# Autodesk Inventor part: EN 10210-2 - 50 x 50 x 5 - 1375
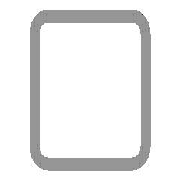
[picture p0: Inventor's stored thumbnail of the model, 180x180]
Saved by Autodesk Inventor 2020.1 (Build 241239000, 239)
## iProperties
IsCustomPart: 1
_CCFamilyMember: 16
_CCFamilyDisplayName: DIN EN 10210-2 (USAS B17.1 quadratisch) - Rohrleitung — In Klammern angegebene Größen wurden aufgehoben
_FrameMemberDoc: Frame Member File
_Version: 15.0.0
_GetPNFromCC: 1
Created: 2019-01
Part Number: EN 10210-2 - 50 x 50 x 5 - 1375
Material: Stahl, weich
Description: Rohrleitung
Document SubType Name: Modeling
Standard: DIN
Designer: lutzd
Standard Revision: 2006-07
Standards Organization: DIN
Language: de-DE
Size Designation: 50 x 50 x 5
Categories: <MemberInstance><Categories><Category DisplayName="Profile" InternalName="089c4875-fa83-4c05-b084-43b9cc11f5ed" Mnemonic="GRDR"><CategoryParameter DisplayName="
Stock Number: 50 x 50 x 5
Mass: 9422.11 g
Surface Area: 4673.09 cm^2
Volume: 1200.27 cm^3
Density: 7.85 g/cm^3
Appearance: Semi-Polished(8)
G_L: 1375,000 mm
G_W: 50,000 mm
G_H: 50,000 mm
DocNumber: ADSK-014303
Folder: .
Dimensions: 50x50x1375 mm
Mass: 9,422 kg
VLT_Material: Stahl, weich
Title: Profil-Bauteil
Author: lutzd
Revision Number: -
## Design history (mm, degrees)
node "Startebene"
node "Endebene"
sketch "Skizze"
  geometry: L1 (-25, -17.5)-(-25, 17.5); L2 (-17.5, 25)-(17.5, 25); L3 (25, 17.5)-(25, -17.5); L4 (17.5, -25)-(-17.5, -25); L5 (-15, 20)-(15, 20); L6 (20, 15)-(20, -15); L7 (15, -20)-(-15, -20); L8 (-20, -15)-(-20, 15); L9 (0, 37.175)-(0, -37.175) reference; L10 (-37.175, 0)-(37.175, 0) reference; A1 r 7.5 centre (-17.5, -17.5) between (-25, -17.5) and (-17.5, -25); A2 r 7.5 centre (-17.5, 17.5) between (-17.5, 25) and (-25, 17.5); A3 r 7.5 centre (17.5, 17.5) between (25, 17.5) and (17.5, 25); A4 r 7.5 centre (17.5, -17.5) between (17.5, -25) and (25, -17.5); A5 r 5 centre (-15, -15) between (-20, -15) and (-15, -20); A6 r 5 centre (-15, 15) between (-15, 20) and (-20, 15); A7 r 5 centre (15, 15) between (20, 15) and (15, 20); A8 r 5 centre (15, -15) between (15, -20) and (20, -15)
  constraints: 16 end point, 16 point on circle, 16 tangent, 8 centre point, 6 equal radius, 4 parallel, 2 perpendicular, 2 other
  dimensions: "d7" = 7.5 radius of A1 (= G_IR); "d10" = 50 distance between parallel lines of L2 L4 (= G_H); "d11" = 50 distance between parallel lines of L1 L3 (= G_W); "d12" = 5 distance between parallel lines of L3 L6 (= G_T); "d15" = 25 distance between parallel lines of L2 L10 (= 0.5 x d10); "d16" = 25 distance between parallel lines of L9 L3 (= 0.5 x d11); "d19" = 5 radius of A5 (= G_T); "d20" = 5 distance between parallel lines of L4 L7 (= G_T)
extrude "Körper" new body sketch "Skizze" stored distance "d3" = 1375 (= G_L); taper "d4" = 0 deg
node "Driven Length"
  sketch "Sketch3"
    geometry: L1 (0, 0)-(10, 0) reference
    constraints: 2 end point, 1 horizontal
  workplane "Work Plane3"
  sketch "Sketch4"
    geometry: L1 (-2, 0)-(12, 0) reference; L2 (-2, 1375)-(12, 1375) reference
    dimensions: "d18" = 1375 distance between parallel lines of L1 L2 (derived)
sketch "Skizze5"
  geometry: L1 (-29.5, 785)-(-5.5, 785); L2 (-35, 0)-(0, 0) reference; 5 further points
  constraints: 2 coincident, 2 end point, 2 midpoint, 1 horizontal, 1 vertical alignment
  dimensions: "d21" = 785 distance between parallel lines of L2 L1; "d22" = 24 distance of L1.start L1.end
hole "Bohrung1" sketch "Skizze5" at (-29.5, 785), (-5.5, 785) diameter "d23" = 6.647; stored, may be unused: countersink angle "d27" = 90 deg, drill point angle "d29" = 118 deg; dims "d24" = 16, "d25" = 4, "d26" = 2, "d28" = 8
body "Solid1"
other parameters: "G_W" = 50 [user parameter; used in 1 equation term], "G_H" = 50 [user parameter; used in 1 equation term], "G_T" = 5 [user parameter; used in 3 equation terms], "G_IR" = 7.5 [user parameter; used in 1 equation term], "G_L" = 1375 (= d18) [user parameter; used in 1 equation term], "G_OFFSET_START" = 0 [user parameter; used in 1 equation term], "G_OFFSET_END" = 0 [user parameter; used in 1 equation term], "d13" = 0 (computed from G_OFFSET_START), "d14" = 1375 (= G_OFFSET_END + B_L), "B_L" = 1375 [user parameter; used in 1 equation term], "d17" = 90 deg
